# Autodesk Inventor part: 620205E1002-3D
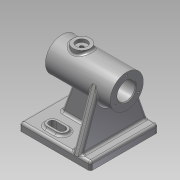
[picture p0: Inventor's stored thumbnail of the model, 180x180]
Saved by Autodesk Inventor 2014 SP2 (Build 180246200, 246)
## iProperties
Created: 2022-02
Part Number: 620205E1002-3D
Material: 강철
Document SubType Name: Modeling
Designer: 거성
Density: 7.85 g/cm^3
Appearance: 강철
Author: 거성
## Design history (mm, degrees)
sketch "스케치1"
  geometry: L1 (-41, 0)-(41, 0); L2 (-41, 14.5)-(-41, 21); L3 (-41, 21)-(41, 21); L4 (41, 21)-(41, 11.5); L5 (41, 11.5)-(21, 11.5); L6 (21, 11.5)-(21, 14.5); L7 (21, 14.5)-(-41, 14.5); 2 further points
  constraints: 14 end point, 4 parallel, 2 perpendicular, 2 vertical alignment, 1 coincident, 1 horizontal, 1 midpoint
  dimensions: "d0" = 82 distance of L1.start L1.end; "d1" = 42 diameter of L3 L1; "d2" = 29 diameter of L7 L1; "d3" = 23 diameter of L5 L1; "d4" = 62 distance of L6.end L2.start
revolve "회전1" sketch "스케치1" stored, may be unused: angle "d5" = 90 deg
node "작업 평면1"
sketch "스케치2"
  geometry: L1 (-43, -58)-(43, -58); L2 (43, -58)-(43, -68); L3 (43, -68)-(-43, -68); L4 (-43, -68)-(-43, -58); 2 further points
  constraints: 8 end point, 2 parallel, 1 horizontal, 1 midpoint, 1 perpendicular, 1 vertical alignment
  dimensions: "d7" = 10 distance between parallel lines of L3 L1; "d8" = 68 distance from line of L3 point (0, 0); "d9" = 86 distance between parallel lines of L2 L4
extrude "돌출1" join sketch "스케치2" distance "d10" = 90; taper "d11" = 0 deg
node "작업 평면2"
node "작업 평면3"
node "작업 평면5"
  node "작업 평면4"
sketch "스케치5"
  geometry: L1 (41, 21)-(41, -21) reference; C1 r 11 at (16, 0); 1 further point
  constraints: 1 centre point, 1 horizontal alignment
  dimensions: "d24" = 22 diameter of C1; "d25" = 25 distance from line of C1.centre L1
extrude "돌출3" join sketch "스케치5" stored distance "d26" = 10; taper "d27" = 0 deg
sketch "스케치6"
  geometry: C1 r 11 at (0, 0) reference; 2 further points
  constraints: 1 coincident
hole "구멍1" sketch "스케치6" at (0, 0) diameter "d28" = 4.917; stored, may be unused: countersink angle "d32" = 90 deg, drill point angle "d34" = 118 deg; dims "d29" = 10, "d30" = 14, "d31" = 4, "d33" = 20
sketch "스케치7" dims "d35" = 34
  geometry: C1 r 21 at (0, 0) reference; 2 further points
  constraints: 2 vertical alignment, 1 coincident, 2 other
hole "구멍2" sketch "스케치7" at (0, 17) diameter "d36" = 2.459; stored, may be unused: countersink angle "d40" = 90 deg, drill point angle "d42" = 118 deg; dims "d37" = 8, "d38" = 14, "d39" = 4, "d41" = 9.5
sketch "스케치8" dims "d46" = 36
  geometry: C1 r 21 at (0, 0) reference; C2 r 14.5 at (0, 0) reference; 2 further points
  constraints: 2 vertical alignment, 1 coincident, 2 other
hole "구멍3" sketch "스케치8" at (0, 18) diameter "d47" = 2.459; stored, may be unused: countersink angle "d51" = 90 deg, drill point angle "d53" = 118 deg; dims "d48" = 8, "d49" = 14, "d50" = 4, "d52" = 9.5
sketch "스케치9"
  geometry: L1 (15, 48)-(67, 48) reference; L2 (90, 86)-(0, 86) reference; L3 (0, 0)-(0, 86) reference; L4 (90, 0)-(0, 0) reference; L5 (26, 70)-(38, 70); L6 (26, 63)-(38, 63); L7 (38, 77)-(26, 77); L8 (26, 16)-(38, 16); L9 (26, 9)-(38, 9); L10 (38, 23)-(26, 23); A1 r 7 centre (26, 70) between (26, 77) and (26, 63); A2 r 7 centre (38, 70) between (38, 63) and (38, 77); A3 r 7 centre (26, 16) between (26, 23) and (26, 9); A4 r 7 centre (38, 16) between (38, 9) and (38, 23); 5 further points
  constraints: 16 end point, 8 point on circle, 8 tangent, 4 centre point, 4 parallel, 2 midpoint
  dimensions: "d57" = 14 distance between parallel lines of L6 L7; "d58" = 26 dimension on A1 A2; "d59" = 26 distance from line of L3 L5.start; "d60" = 16 distance from line of L2 point (32, 70); "d61" = 26 dimension on A4 A3; "d62" = 14 distance between parallel lines of L9 L10; "d63" = 26 distance from line of L3 L8.start; "d64" = 16 distance from line of L4 point (32, 16)
extrude "돌출4" join sketch "스케치9" distance "d65" = 3; taper "d66" = 0 deg
sketch "스케치10"
  geometry: L1 (26, 63)-(38, 63) reference; L2 (26, 9)-(38, 9) reference; L3 (38, 23)-(26, 23) reference; L4 (26, 70)-(38, 70); L5 (26, 65.5)-(38, 65.5); L6 (38, 74.5)-(26, 74.5); L7 (26, 16)-(38, 16); L8 (26, 11.5)-(38, 11.5); L9 (38, 20.5)-(26, 20.5); A1 r 7 centre (38, 70) between (38, 63) and (38, 77) reference; A2 r 7 centre (38, 16) between (38, 9) and (38, 23) reference; A3 r 7 centre (26, 16) between (26, 23) and (26, 9) reference; A4 r 4.5 centre (26, 70) between (26, 74.5) and (26, 65.5); A5 r 4.5 centre (38, 70) between (38, 65.5) and (38, 74.5); A6 r 4.5 centre (26, 16) between (26, 20.5) and (26, 11.5); A7 r 4.5 centre (38, 16) between (38, 11.5) and (38, 20.5); 5 further points
  constraints: 16 end point, 8 point on circle, 8 tangent, 4 centre point, 4 midpoint, 4 parallel, 2 horizontal alignment, 2 vertical alignment
  dimensions: "d67" = 9 distance between parallel lines of L5 L6; "d68" = 9 distance between parallel lines of L8 L9; "d69" = 21 dimension on A5 A4; "d70" = 21 dimension on A6 A7
extrude "돌출5" cut sketch "스케치10" distance "d71" = 20; taper "d72" = 0 deg
fillet "모깎기1" dims "d73" = 3
fillet "모깎기2" dims "d74" = 3
node "작업 평면6"
sketch "스케치11"
  geometry: L1 (43, -61)-(43, -68) reference; L2 (43, -68)-(-43, -68) reference; L3 (-43, -68)-(-43, -61) reference; L4 (-40, -58)-(40, -58) reference; L5 (-19.86, 6.826)-(-42.837, -60.025); L6 (19.86, 6.826)-(42.837, -60.025); C1 r 11.5 at (0, 0) reference; A1 r 3 centre (40, -61) between (43, -61) and (40, -58) reference; A2 r 3 centre (-40, -61) between (-40, -58) and (-43, -61) reference; A3 r 21 centre (0, 0) between (-19.86, 6.826) and (19.86, 6.826) reference; A4 r 21 centre (0, 0) between (-19.86, 6.826) and (19.86, 6.826); 1 further point
  constraints: 6 point on circle, 4 end point, 4 tangent, 1 centre point, 1 coincident
extrude "돌출7" join sketch "스케치11" distance "d78" = 10; taper "d79" = 0 deg
node "작업 평면7"
sketch "스케치12"
  geometry: L1 (26, 88)-(30.541, 88) reference; L2 (30.541, 88)-(30.541, 82.5) reference; L3 (30.541, 82.5)-(8, 82.5) reference; L4 (8, 82.5)-(8, 84.771) reference; L5 (8, 84.771)-(17.5, 84.771) reference; L6 (17.5, 84.771)-(18.239, 86) reference; L7 (18.239, 86)-(17.5, 87.23) reference; L8 (17.5, 87.23)-(8, 87.23) reference; L9 (8, 87.23)-(8, 89) reference; L10 (8, 89)-(19, 89) reference; L11 (22, 92)-(26, 92) reference; L12 (26, 92)-(26, 88) reference; L13 (35.458, 88)-(40, 88) reference; L14 (40, 88)-(40, 92) reference; L15 (40, 92)-(44, 92) reference; L16 (47, 89)-(90, 89) reference; L17 (90, 89)-(90, 86.23) reference; L18 (90, 86.23)-(80.5, 86.23) reference; L19 (80.5, 86.23)-(79.761, 85) reference; L20 (79.761, 85)-(80.5, 83.771) reference; L21 (80.5, 83.771)-(90, 83.771) reference; L22 (90, 83.771)-(90, 79.5) reference; L23 (90, 79.5)-(70, 79.5) reference; L24 (70, 79.5)-(70, 82.5) reference; L25 (70, 82.5)-(35.458, 82.5) reference; L26 (35.458, 82.5)-(35.458, 88) reference; L27 (87, 7)-(87, 0) reference; L28 (87, 0)-(-3, 0) reference; L29 (-3, 0)-(-3, 7) reference; L30 (0, 10)-(64, 10) reference; L31 (64, 10)-(64, 47) reference; L32 (64, 47)-(8, 47) reference; L33 (8, 47)-(8, 53.5) reference; L34 (8, 53.5)-(70, 53.5) reference; L35 (70, 53.5)-(70, 56.5) reference; L36 (70, 56.5)-(90, 56.5) reference; L37 (90, 56.5)-(90, 47) reference; L38 (90, 47)-(74, 47) reference; L39 (74, 47)-(74, 10) reference; L40 (74, 10)-(84, 10) reference; L41 (12, 10)-(25.467, 47); A1 r 3 centre (84, 7) between (87, 7) and (84, 10) reference; A2 r 3 centre (0, 7) between (0, 10) and (-3, 7) reference; 1 further point
  constraints: 2 end point, 2 point on line, 2 other
  dimensions: "d80" = 15 distance from line of L29 L41.start; "d81" = 110 deg angle of L30 L41
feature "리브2" sketch "스케치12" dims "d82" = 1, "d83" = 10, "d84" = 0, "d85" = 0, "d86" = 1, "d87" = 1
fillet "모깎기3" dims "d88" = 3
fillet "모깎기4" dims "d89" = 3
chamfer "모따기1" distance "d90" = 1; stored, may be unused: second distance "d91" = 2, angle "d92" = 45 deg
node "솔리드1"
pattern_circular "원형 패턴1" dims angle "d44" = 360 deg
pattern_circular "원형 패턴2" dims angle "d55" = 360 deg
node "투영된 루프1"
node "절단 모서리 투영3"
node "절단 모서리 투영4"
other parameters: "d6" = -3, "d12" = -16, "d23" = 3, "d77" = -16
